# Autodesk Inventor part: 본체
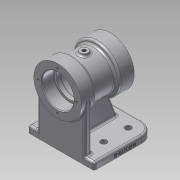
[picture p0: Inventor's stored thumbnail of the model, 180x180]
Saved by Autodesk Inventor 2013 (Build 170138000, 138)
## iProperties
Created: 2020-06
Part Number: 본체
Material: 알루미늄 6061
Document SubType Name: Modeling
Designer: a
Density: 1 g/cm^3
Author: a
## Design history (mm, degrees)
sketch "스케치1"
  geometry: L1 (0, 39)-(0, -39); L2 (0, 39)-(35, 39); L3 (35, 39)-(35, 17); L4 (35, 17)-(29, 17); L5 (29, 17)-(29, -17); L6 (29, -17)-(35, -17); L7 (35, -17)-(35, -39); L8 (35, -39)-(0, -39); 2 further points
  constraints: 16 end point, 4 parallel, 2 perpendicular, 1 coincident, 1 collinear, 1 midpoint, 1 vertical
  dimensions: "d0" = 78 distance of L1.start L1.end; "d2" = 70 diameter of L3 L1; "d3" = 70 diameter of L7 L1; "d4" = 58 diameter of L5 L1; "d5" = 22 distance of L2.end L3.end; "d6" = 22 distance of L6.end L7.end
revolve "회전1" sketch "스케치1" stored, may be unused: angle "d7" = 90 deg
sketch "스케치2"
  geometry: L1 (-35, 39)-(35, 39) reference; L2 (35, 39)-(35, 17) reference; L3 (35, 17)-(29, 17) reference; L4 (29, 17)-(29, -17) reference; L5 (29, -17)-(35, -17) reference; L6 (35, -17)-(35, -39) reference; L7 (35, -39)-(-35, -39) reference; L8 (-35, -39)-(-35, -17) reference; L9 (-35, -17)-(-29, -17) reference; L10 (-29, -17)-(-29, 17) reference; L11 (-29, 17)-(-35, 17) reference; L12 (-35, 17)-(-35, 39) reference; L13 (0, 39)-(0, -39); L14 (0, 39)-(23.5, 39); L15 (23.5, 39)-(23.5, 21); L16 (23.5, 21)-(20, 21); L17 (20, 21)-(20, 15); L18 (20, 15)-(23, 15); L19 (23, 15)-(23, -15); L20 (23, -15)-(20, -15); L21 (20, -15)-(20, -21); L22 (20, -21)-(23.5, -21); L23 (23.5, -21)-(23.5, -39); L24 (0, -39)-(23.5, -39); 1 further point
  constraints: 24 end point, 6 parallel, 4 perpendicular, 2 midpoint, 2 point on line
  dimensions: "d8" = 47 diameter of L15 L13; "d10" = 47 diameter of L23 L13; "d11" = 46 diameter of L19 L13; "d12" = 40 diameter of L17 L13; "d13" = 40 diameter of L21 L13; "d14" = 18 distance of L14.end L15.end; "d15" = 6 distance of L16.end L17.end; "d16" = 30 distance of L18.end L19.end; "d17" = 18 distance of L22.end L23.end
revolve "회전2" sketch "스케치2" stored, may be unused: angle "d18" = 90 deg
node "작업 평면2"
sketch "스케치4"
  geometry: C1 r 6 at (0, 0); 1 further point
  constraints: 1 centre point, 1 coincident
  dimensions: "d22" = 12 diameter of C1
extrude "돌출1" join sketch "스케치4" stored distance "d23" = 10; taper "d24" = 0 deg
sketch "스케치5"
  geometry: C1 r 6 at (0, 0) reference; 1 further point
  constraints: 1 coincident
hole "구멍1" sketch "스케치5" at (0, 0) diameter "d25" = 5.188; stored, may be unused: countersink angle "d29" = 90 deg, drill point angle "d31" = 118 deg; dims "d26" = 30, "d27" = 4, "d28" = 2, "d30" = 30
sketch "스케치6" dims "d32" = 57
  geometry: C1 r 23.5 at (0, 0) reference; C2 r 35 at (0, 0) reference; 2 further points
  constraints: 2 vertical alignment, 1 coincident, 2 other
hole "구멍2" sketch "스케치6" at (0, 28.5) diameter "d33" = 3.242; stored, may be unused: countersink angle "d37" = 90 deg, drill point angle "d39" = 118 deg; dims "d34" = 10, "d35" = 4, "d36" = 2, "d38" = 12
node "작업 평면3"
sketch "스케치7"
  geometry: L1 (-35, 39)-(35, 39) reference; L2 (-49, 34)-(49, 34); L3 (49, 34)-(49, -56); L4 (49, -56)-(-49, -56); L5 (-49, -56)-(-49, 34); 2 further points
  constraints: 8 end point, 2 parallel, 1 horizontal, 1 midpoint, 1 perpendicular, 1 vertical alignment
  dimensions: "d44" = 98 distance of L3.end L4.end; "d45" = 90 distance of L2.end L3.end; "d46" = 5 distance between parallel lines of L1 L2
extrude "돌출2" join sketch "스케치7" distance "d47" = 10; taper "d48" = 0 deg
fillet "모깎기1" dims "d49" = 20
sketch "스케치8"
  geometry: C1 r 4.5 at (-29, 36); C2 r 4.5 at (29, 36); C3 r 4.5 at (-29, 0); C4 r 4.5 at (29, 0); A1 r 20 centre (-29, 36) between (-29, 56) and (-49, 36) reference; A2 r 20 centre (29, 36) between (49, 36) and (29, 56) reference; 1 further point
  constraints: 4 centre point, 2 coincident, 2 vertical alignment
  dimensions: "d53" = 9 diameter of C1; "d54" = 9 diameter of C2; "d55" = 9 diameter of C3; "d56" = 9 diameter of C4; "d57" = 36 distance of C3.centre A1.centre; "d58" = 36 distance of C4.centre A2.centre
extrude "돌출3" cut sketch "스케치8" distance "d59" = 10; taper "d60" = 0 deg
sketch "스케치9"
  geometry: L1 (-49, -34)-(49, -34) reference; L2 (-35, -34)-(35, -34); L3 (35, -34)-(35, -24); L4 (35, -24)-(-35, -24); L5 (-35, -24)-(-35, -34); 2 further points
  constraints: 8 end point, 2 parallel, 1 horizontal, 1 midpoint, 1 perpendicular, 1 point on line, 1 vertical alignment
  dimensions: "d61" = 70 distance of L3.end L4.end; "d63" = 10 distance of L4.end L2.start
extrude "돌출4" join sketch "스케치9" stored distance "d64" = 10; taper "d65" = 0 deg
sketch "스케치10"
  geometry: L1 (29, 6)-(32, 6) reference; L2 (32, 6)-(32, 2.594) reference; L3 (32, 2.594)-(23, 2.594) reference; L4 (23, 2.594)-(23, 15) reference; L5 (23, 15)-(20, 15) reference; L6 (20, 15)-(20, 21) reference; L7 (20, 21)-(23.5, 21) reference; L8 (23.5, 21)-(23.5, 39) reference; L9 (23.5, 39)-(26.879, 39) reference; L10 (26.879, 39)-(26.879, 27) reference; L11 (26.879, 27)-(28.5, 26.026) reference; L12 (28.5, 26.026)-(30.121, 27) reference; L13 (30.121, 27)-(30.121, 39) reference; L14 (30.121, 39)-(35, 39) reference; L15 (35, 39)-(35, 17) reference; L16 (35, 17)-(29, 17) reference; L17 (29, 17)-(29, 6) reference; L18 (23.5, -39)-(23.5, -21) reference; L19 (23.5, -21)-(20, -21) reference; L20 (20, -21)-(20, -15) reference; L21 (20, -15)-(23, -15) reference; L22 (23, -15)-(23, -2.594) reference; L23 (23, -2.594)-(32, -2.594) reference; L24 (32, -2.594)-(32, -6) reference; L25 (32, -6)-(29, -6) reference; L26 (29, -6)-(29, -17) reference; L27 (29, -17)-(35, -17) reference; L28 (35, -17)-(35, -39) reference; L29 (35, -39)-(30.121, -39) reference; L30 (30.121, -39)-(30.121, -27) reference; L31 (30.121, -27)-(28.5, -26.026) reference; L32 (28.5, -26.026)-(26.879, -27) reference; L33 (26.879, -27)-(26.879, -39) reference; L34 (26.879, -39)-(23.5, -39) reference; L35 (-80, -56)-(-80, 34) reference; L36 (-80, 34)-(-35, 34) reference; L37 (-35, 34)-(-35, 39) reference; L38 (-35, 39)-(-30.121, 39) reference; L39 (-30.121, 39)-(-30.121, 27) reference; L40 (-30.121, 27)-(-28.5, 26.026) reference; L41 (-28.5, 26.026)-(-26.879, 27) reference; L42 (-26.879, 27)-(-26.879, 39) reference; L43 (-26.879, 39)-(-23.5, 39) reference; L44 (-23.5, 39)-(-23.5, 21) reference; L45 (-23.5, 21)-(-20, 21) reference; L46 (-20, 21)-(-20, 15) reference; L47 (-20, 15)-(-23, 15) reference; L48 (-23, 15)-(-23, -15) reference; L49 (-23, -15)-(-20, -15) reference; L50 (-20, -15)-(-20, -21) reference; L51 (-20, -21)-(-23.5, -21) reference; L52 (-23.5, -21)-(-23.5, -39) reference; L53 (-23.5, -39)-(-26.879, -39) reference; L54 (-26.879, -39)-(-26.879, -27) reference; L55 (-26.879, -27)-(-28.5, -26.026) reference; L56 (-28.5, -26.026)-(-30.121, -27) reference; L57 (-30.121, -27)-(-30.121, -39) reference; L58 (-30.121, -39)-(-35, -39) reference; L59 (-35, -39)-(-35, -17) reference; L60 (-35, -17)-(-29, -17) reference; L61 (-29, -17)-(-29, 17) reference; L62 (-29, 17)-(-35, 17) reference; L63 (-35, 17)-(-35, 24) reference; L64 (-35, 24)-(-70, 24) reference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; 1 further point
  constraints: 2 end point, 2 point on line
  dimensions: "d66" = 12 distance of L65.end L67.start; "d67" = 70 deg angle of L67 L65
feature "리브1" sketch "스케치10" dims "d68" = 1, "d69" = 10, "d70" = 0, "d71" = 0, "d72" = 1, "d73" = 1
sketch "스케치11"
  geometry: 3 further points
  constraints: 1 other
  dimensions: "d74" = 45 horizontal distance of point (0, 0) point (45, 4); "d75" = 4 vertical distance of point (0, 0) point (45, 4)
feature "엠보싱1" sketch "스케치11" dims "d76" = 0.5, "d77" = 0
fillet "모깎기2" dims "d78" = 3
fillet "모깎기3" dims "d79" = 0.3
chamfer "모따기1" distance "d80" = 1; stored, may be unused: second distance "d81" = 2, angle "d82" = 45 deg
fillet "모깎기4" dims "d83" = 3
fillet "모깎기5" dims "d84" = 3
fillet "모깎기6" dims "d85" = 3
fillet "모깎기7" dims "d86" = 3
fillet "모깎기8" dims "d87" = 3
fillet "모깎기9" dims "d88" = 3
fillet "모깎기10" dims "d89" = 3
fillet "모깎기11" dims "d90" = 3
fillet "모깎기12" dims "d91" = 3
fillet "모깎기13" dims "d92" = 3
node "솔리드1"
pattern_circular "원형 패턴1" dims angle "d41" = 360 deg
mirror "대칭1"
node "절단 모서리 투영1"
node "절단 모서리 투영2"
other parameters: "d21" = 32
